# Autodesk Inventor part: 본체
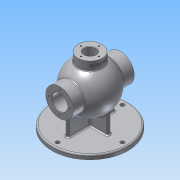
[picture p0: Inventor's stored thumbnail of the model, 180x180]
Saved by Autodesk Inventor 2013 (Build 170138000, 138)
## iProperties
Created: 2020-08
Part Number: 본체
Material: 알루미늄 6061
Document SubType Name: Modeling
Designer: user
Density: 2.71 g/cm^3
Mass: 1759.15 g
Surface Area: 1342.58 cm^2
Volume: 649.134 cm^3
Author: user
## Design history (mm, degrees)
revolve "회전1" stored, may be unused: angle "d10" = 90 deg
node "작업 평면1"
sketch "스케치2"
  geometry: C1 r 85 at (0, 0); 1 further point
  constraints: 1 centre point, 1 coincident
  dimensions: "d12" = 170 diameter of C1
extrude "돌출1" join sketch "스케치2" distance "d13" = 10; taper "d14" = 0 deg
sketch "스케치3"
  geometry: C1 r 85 at (0, 0) reference; 4 further points
  constraints: 1 vertical alignment, 5 other
  dimensions: "d15" = 72.5 distance of point (0, 72.5) C1.centre; "d18" = 360 deg dimension on C1.centre point (0, 72.5) (derived)
hole "구멍1" sketch "스케치3" at (0, 72.5), (-72.5, 0), (0, -72.5), (72.5, 0) diameter "d20" = 9; stored, may be unused: countersink angle "d24" = 90 deg, drill point angle "d26" = 118 deg; dims "d21" = 6, "d22" = 4, "d23" = 2, "d25" = 8
sketch "스케치4"
  geometry: L1 (4, -52)-(-4, -52); L2 (-4, -52)-(-4, 52); L3 (-4, 52)-(4, 52); L4 (4, 52)-(4, -52); L5 (4, -52)-(-4, 52); L6 (-4, -52)-(4, 52); L7 (-43, 4)-(43, 4); L8 (43, 4)-(43, -4); L9 (43, -4)-(-43, -4); L10 (-43, -4)-(-43, 4); L11 (-43, 4)-(43, -4); L12 (43, 4)-(-43, -4); C1 r 85 at (0, 0) reference
  constraints: 24 end point, 4 midpoint, 4 parallel, 2 horizontal, 2 perpendicular
  dimensions: "d27" = 104 distance of L3.end L1.start; "d29" = 8 distance of L2.end L3.end; "d30" = 86 distance of L8.end L9.end; "d31" = 8 distance of L9.end L7.start
extrude "돌출2" join sketch "스케치4" stored distance "d32" = 10; taper "d33" = 0 deg
sketch "스케치5"
  geometry: C1 r 31 at (0, 0) reference; 4 further points
  constraints: 1 vertical alignment, 5 other
  dimensions: "d34" = 24 distance of point (0, 24) C1.centre; "d37" = 360 deg dimension on C1.centre point (0, 24) (derived)
hole "구멍2" sketch "스케치5" at (0, 24), (-24, 0), (0, -24), (24, 0) diameter "d39" = 3.242; stored, may be unused: countersink angle "d43" = 90 deg, drill point angle "d45" = 118 deg; dims "d40" = 12, "d41" = 4, "d42" = 2, "d44" = 15
node "작업 평면2"
sketch "스케치6"
  geometry: C1 r 27 at (0, 0); 1 further point
  constraints: 1 centre point, 1 coincident
  dimensions: "d47" = 54 diameter of C1
extrude "돌출3" join sketch "스케치6" stored distance "d48" = 10; taper "d49" = 0 deg
sketch "스케치7"
  geometry: C1 r 27 at (0, 0) reference; C2 r 13 at (0, 0)
  constraints: 1 centre point, 1 coincident
  dimensions: "d50" = 26 diameter of C2
extrude "돌출4" cut sketch "스케치7" stored distance "d51" = 10; taper "d52" = 0 deg
sketch "스케치8"
  geometry: C1 r 13 at (0, 0) reference; 4 further points
  constraints: 1 vertical alignment, 5 other
  dimensions: "d53" = 20 distance of C1.centre point (0, 20); "d56" = 360 deg dimension on C1.centre point (0, 20) (derived)
hole "구멍3" sketch "스케치8" at (0, 20), (-20, 0), (0, -20), (20, 0) diameter "d58" = 3.242; stored, may be unused: countersink angle "d62" = 90 deg, drill point angle "d64" = 118 deg; dims "d59" = 12, "d60" = 4, "d61" = 2, "d63" = 15
chamfer "모따기1" distance "d65" = 1; stored, may be unused: second distance "d66" = 2, angle "d67" = 45 deg
fillet "모깎기1" dims "d68" = 3
fillet "모깎기2" dims "d69" = 3
fillet "모깎기3" dims "d70" = 3
node "작업 평면3"
node "작업 평면4"
node "작업 평면5"
sketch "스케치11"
  geometry: L1 (0, 27)-(-17.714, 27) reference; L2 (0, 27)-(0, -27) reference; 2 further points
  constraints: 1 other
  dimensions: "d82" = 9 distance from line of point (-9, 0) L2; "d83" = 27 distance from line of point (-9, 0) L1
feature "엠보싱3" sketch "스케치11" dims "d0" = 136, "d2" = 106, "d3" = 86, "d5" = 62, "d6" = 35, "d18" = 360 deg (derived), "d79" = 37, "d80" = 16, "d81" = 1.75, "d84" = 0.5, "d85" = 0
chamfer "모따기2" distance "d86" = 1; stored, may be unused: second distance "d87" = 2, angle "d88" = 45 deg
node "솔리드1"
mirror "대칭1"
sketch "스케치1"
  geometry: L1 (0, 68)-(0, -68); L2 (0, 68)-(31, 68); L3 (31, -68)-(0, -68); L4 (31, 42.988)-(31, 68); L5 (31, -68)-(31, -42.988); L6 (17.5, 68)-(17.5, 52); L7 (17.5, 68)-(17.5, 39.278); L8 (17.5, -52)-(18.5, -52); L9 (18.5, -52)-(18.5, -50.25); L10 (18.5, -50.25)-(17.5, -50.25); L11 (17.5, -39.278)-(17.5, -50.25); L12 (17.5, -52)-(17.5, -68); A1 r 53 centre (0, 0) between (31, -42.988) and (31, 42.988); A2 r 43 centre (0, 0) between (17.5, -39.278) and (17.5, 39.278); 2 further points
  constraints: 24 end point, 7 collinear, 6 perpendicular, 4 point on circle, 3 coincident, 3 parallel, 2 centre point, 2 point on line, 1 midpoint, 1 vertical
  dimensions: "d0" = 136 distance of L1.start L1.end; "d2" = 106 diameter of A1; "d3" = 86 diameter of A2; "d5" = 62 diameter of L4 L1; "d6" = 35 diameter of L6 L1; "d79" = 37 diameter of L9 L1; "d80" = 16 distance of L8.start L12.end; "d81" = 1.75 distance of L8.end L9.end
other parameters: "d4" = 62, "d11" = -85, "d46" = 65
